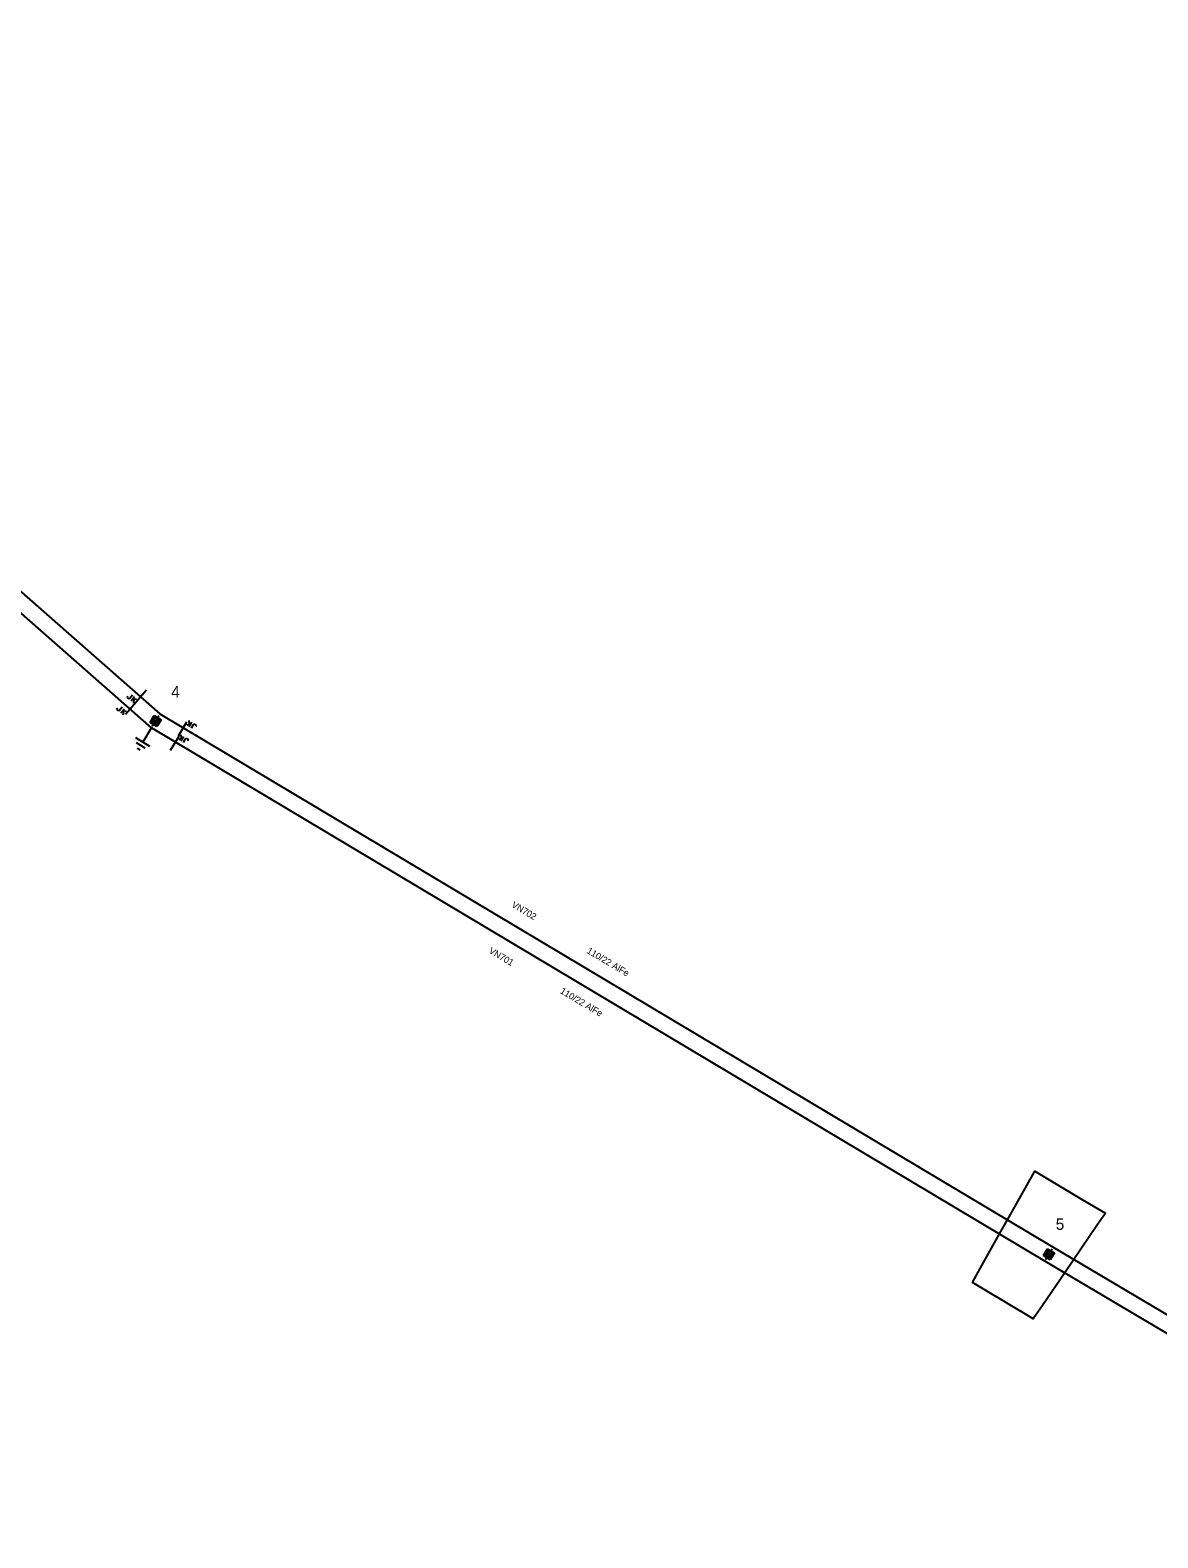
# Model space of a CAD drawing. Extents: x -545588 to -543214, y -1196037 to -1194452.
# Drawn here: x -544989.1 to -544817.1, y -1195194.1 to -1194964.1 of the extents above; entities that cross this region are included whole.
import ezdxf

# ---------------------------------------------------------------- set-up
doc = ezdxf.new("R2010")
doc.units = 0
for name, color, linetype in [('Vrstva 1', 7, 'Continuous'), ('Vrstva 13', 7, 'Continuous'), ('Vrstva 14', 7, 'Continuous'), ('Vrstva 15', 7, 'Continuous'), ('Vrstva 18', 7, 'Continuous'), ('Vrstva 2', 7, 'Continuous'), ('Vrstva 3', 7, 'Continuous'), ('Vrstva 35', 7, 'Continuous')]:
    doc.layers.add(name, color=color, linetype=linetype)

# ---------------------------------------------------------------- blocks, each defined once
blk = doc.blocks.new('VN840')
at = {"layer": 'Vrstva 15'}
for points in [[(-0.01, 1.41), (-0.01, -1.09)], [(-1.51, -1.24), (-1.51, -1.15)], [(-1.48, -1.35), (-1.51, -1.24)], [(-1.33, -1.42), (-1.48, -1.35)], [(-1.27, -1.42), (-1.33, -1.42)], [(-1.13, -1.35), (-1.27, -1.42)], [(-1.09, -1.24), (-1.13, -1.35)], [(-1.09, -0.59), (-1.09, -1.24)], [(-0.68, -0.59), (-0.68, -1.42)], [(-0.68, -1.11), (-0.27, -0.59)], [(-0.54, -0.94), (-0.2, -1.42)]]:
    blk.add_lwpolyline(points, dxfattribs=at)
blk = doc.blocks.new('VN810')
at = {"layer": 'Vrstva 14'}
for points in [[(0, -1.25), (0, -3.75)], [(1.25, -3.75), (-1.25, -3.75)], [(0.77, -4.37), (-0.8, -4.37)], [(0, -5), (-0.25, -5)], [(0.27, -5), (0, -5)]]:
    blk.add_lwpolyline(points, dxfattribs=at)
blk = doc.blocks.new('VN470')
at = {"layer": 'Vrstva 2'}
for points in [[(-1.23, 1.22), (1.23, 1.22)], [(-1.23, -1.23), (-1.23, 1.22)], [(-0.92, 0.9), (0.92, 0.9)], [(-0.92, -0.95), (-0.92, 0.9)], [(-0.61, 0.61), (0.61, 0.61)], [(-0.61, -0.62), (-0.61, 0.61)], [(-0.31, -0.27), (-0.31, 0.34)], [(-0.31, 0.34), (0.31, 0.34)], [(0, 1.22), (0, 1.97)], [(0.31, 0.34), (0.31, -0.27)], [(0.61, 0.61), (0.61, -0.62)], [(0.92, 0.9), (0.92, -0.95)], [(1.23, 1.22), (1.23, -1.23)], [(1.23, -1.23), (-1.23, -1.23)], [(0.92, -0.95), (-0.92, -0.95)], [(0.61, -0.62), (-0.61, -0.62)], [(0.31, -0.27), (-0.31, -0.27)], [(0, -1.23), (0, -1.98)]]:
    blk.add_lwpolyline(points, dxfattribs=at)

msp = doc.modelspace()

# ---------------------------------------------------------------- linework, layer by layer
at = {"layer": 'Vrstva 1'}
for points in [[(-543649.39, -1195854.44), (-543751.62, -1195793.1), (-543875.2, -1195719.97), (-544006.92, -1195641.71), (-544142.24, -1195562.12), (-544281.11, -1195480), (-544421.5, -1195396.73), (-544557.6, -1195316.44), (-544689.64, -1195237.57), (-544834.28, -1195151.89), (-544970.6, -1195070.55), (-545089.61, -1194965.95)], [(-545087.98, -1194964.09), (-544969.35, -1195068.41), (-544833.03, -1195149.76), (-544688.41, -1195235.46), (-544556.36, -1195314.32), (-544420.24, -1195394.62), (-544279.84, -1195477.88), (-544141.02, -1195559.94), (-544005.67, -1195639.57), (-543873.94, -1195717.89), (-543750.35, -1195790.92), (-543648.17, -1195852.31)]]:
    msp.add_lwpolyline(points, dxfattribs=at)
at = {"layer": 'Vrstva 35'}
msp.add_lwpolyline([(-544838.62, -1195159.2), (-544845.35, -1195155.18), (-544844.15, -1195153.03), (-544841.19, -1195147.77), (-544839.99, -1195145.61), (-544837.5, -1195141.19), (-544837.03, -1195140.35), (-544835.83, -1195138.2), (-544828.69, -1195142.46), (-544825.06, -1195144.61), (-544826.45, -1195146.65), (-544829.86, -1195151.64), (-544831.25, -1195153.68), (-544834.67, -1195158.68), (-544836.06, -1195160.72), (-544837.5, -1195159.87)], close=True, dxfattribs=at)

# ---------------------------------------------------------------- block references
at = {"layer": 'Vrstva 13', "xscale": 0.49999999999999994, "yscale": 0.5000000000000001}
for p, rotation in [((-544969.99, -1195069.51), 149.1705221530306), ((-544833.68, -1195150.86), 149.35595556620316)]:
    msp.add_blockref('VN470', p, dxfattribs=dict(at, rotation=rotation))
at = {"layer": 'Vrstva 15', "rotation": -30.835922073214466}
msp.add_blockref('VN810', (-544969.99, -1195069.51), dxfattribs=at)
at = {"layer": 'Vrstva 18'}
for p, rotation in [((-544972.28, -1195065.84), -41.32799999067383), ((-544973.87, -1195067.68), -41.31261387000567), ((-544965.76, -1195070.56), 149.13918058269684), ((-544966.97, -1195072.72), 149.147380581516)]:
    msp.add_blockref('VN840', p, dxfattribs=dict(at, rotation=rotation))

# ---------------------------------------------------------------- texts
at = {"layer": 'Vrstva 14'}
for s, p in [('4', (-544967.6, -1195065.93)), ('5', (-544832.63, -1195147.13))]:
    msp.add_text(s, height=1.75, dxfattribs=at).set_placement(p)
at = {"layer": 'Vrstva 2'}
for rotation, p in [(329.172, (-544904.28, -1195104.83)), (329.176, (-544908.35, -1195110.96))]:
    msp.add_text('110/22 AlFe', height=1, rotation=rotation, dxfattribs=at).set_placement(p)
at = {"layer": 'Vrstva 3'}
for s, rotation, p in [('VN702', 329.172, (-544915.76, -1195097.81)), ('VN701', 329.176, (-544919.22, -1195104.83))]:
    msp.add_text(s, height=1, rotation=rotation, dxfattribs=at).set_placement(p)

doc.saveas('drawing.dxf')
